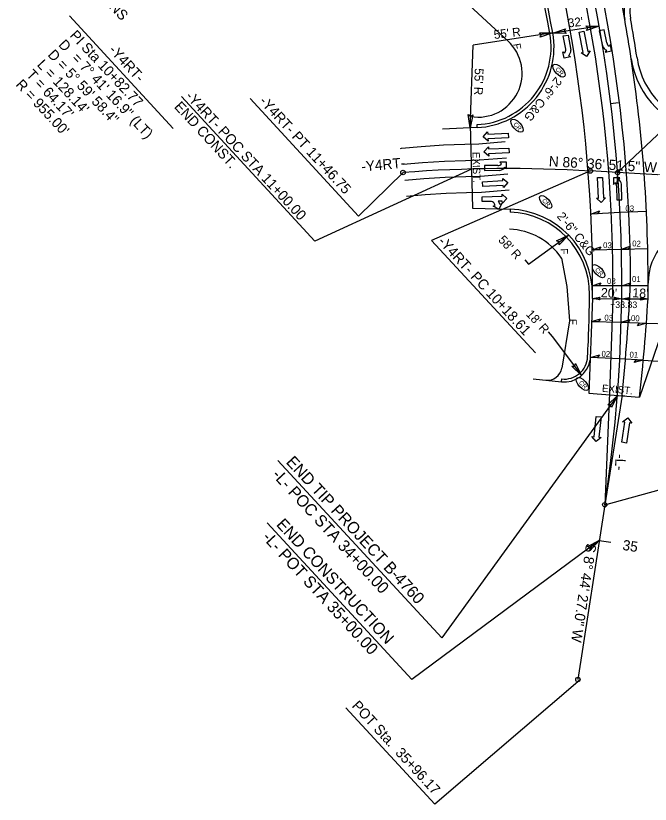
# Model space of a CAD drawing. Extents: x 1702862 to 1704514, y 793768 to 796215.
# Drawn here: x 1703575 to 1704009, y 793768 to 794307 of the extents above; entities that cross this region are included whole.
import ezdxf

# ---------------------------------------------------------------- set-up
doc = ezdxf.new("R2010")
doc.units = 0
for name, color, linetype in [('Exist Horizontal Alignment', 7, 'Continuous'), ('Exist Horizontal Alignment Curve and Spiral Data', 7, 'Continuous'), ('Exist Horizontal Alignment Station Label', 7, 'Continuous'), ('Exist Horizontal Alignment Tick Large', 7, 'Continuous'), ('Prop Conc 2ft 6in Curb and Gutter', 7, 'Continuous'), ('Prop Dimension', 7, 'Continuous'), ('Prop Dimension Text', 7, 'Continuous'), ('Prop DSN Text', 7, 'Continuous'), ('Prop EOT', 7, 'Continuous'), ('Prop Horizontal Alignment', 7, 'Continuous'), ('Prop Horizontal Alignment Curve and Spiral Data', 7, 'Continuous'), ('Prop Horizontal Alignment Direction Label', 7, 'Continuous'), ('Prop Horizontal Alignment Station Label', 7, 'Continuous'), ('Prop Horizontal Alignment Tick Label', 7, 'Continuous'), ('Prop Horizontal Alignment Tick Large', 7, 'Continuous'), ('Prop Horizontal Alignment Tick Small', 7, 'Continuous'), ('Prop Lane Arrow CELL', 7, 'Continuous'), ('Prop Lane Lines', 7, 'Continuous'), ('Prop Leader Line Medium', 7, 'Continuous'), ('Prop Paved Shoulder', 7, 'Continuous'), ('Prop SS Fill Line', 7, 'Continuous'), ('Prop SS Misc', 7, 'Continuous'), ('Prop SS Transition Line', 7, 'Continuous'), ('Prop Superelevation  Arrow CELL', 7, 'Continuous'), ('Prop Superelevation Label', 7, 'Continuous'), ('Prop Terminator CELL', 7, 'Continuous'), ('Prop WCR CELL', 7, 'Continuous')]:
    doc.layers.add(name, color=color, linetype=linetype)

msp = doc.modelspace()

# ---------------------------------------------------------------- linework, layer by layer
at = {"layer": 'Exist Horizontal Alignment'}
msp.add_line((1703986.29, 794199.72), (1703967.71, 794200.82), dxfattribs=at)
msp.add_arc((1703911.32, 793247.48), 955, 86.61431, 94.30234, dxfattribs=at)
at = {"layer": 'Exist Horizontal Alignment Curve and Spiral Data'}
msp.add_line((1703611.73, 794306.9), (1703682.73, 794229.98), dxfattribs=at)
at = {"layer": 'Exist Horizontal Alignment Station Label'}
for p, q in [((1703735.18, 794250.31), (1703809.32, 794169.99)), ((1703809.32, 794169.99), (1703839.67, 794199.79)), ((1703967.71, 794200.82), (1703859.14, 794153.32)), ((1703859.14, 794153.32), (1703930.08, 794076.46))]:
    msp.add_line(p, q, dxfattribs=at)
for centre in [(1703839.67, 794199.79), (1703967.71, 794200.82), (1703986.29, 794199.72)]:
    msp.add_circle(centre, 1.5, dxfattribs=at)
at = {"layer": 'Exist Horizontal Alignment Tick Large'}
msp.add_line((1703986.29, 794199.72), (1703985.82, 794191.73), dxfattribs=at)
at = {"layer": 'Prop Conc 2ft 6in Curb and Gutter'}
for p, q in [((1703890.33, 794230.53), (1703890.23, 794232.53)), ((1703912.86, 794174.66), (1703912.8, 794172.67)), ((1703947.93, 794056.66), (1703948.13, 794058.65))]:
    msp.add_line(p, q, dxfattribs=at)
for centre, radius, start, end in [((1702989.11, 794124.65), 966, 10.14602, 17.69698), ((1703887.83, 794285.48), 53, 272.5979, 10.146), ((1703911.08, 794116.69), 56, 359.5057, 88.2385), ((1702989.11, 794124.65), 978, 357.01557, 359.50571), ((1703949.8, 794074.56), 16, 264.0066, 357.0156)]:
    msp.add_arc(centre, radius, start, end, dxfattribs=at)
at = {"layer": 'Prop Dimension'}
for p, q in [((1703973.64, 794299.88), (1703941.98, 794295.11)), ((1703941.97, 794295.17), (1703887.5, 794286.9)), ((1703885.5, 794230.32), (1703887.5, 794286.9)), ((1703969.03, 794113.76), (1703989.05, 794113.54)), ((1703989.05, 794113.54), (1704007.05, 794113.34))]:
    msp.add_line(p, q, dxfattribs=at)
for points in [[(1703922.81, 794140.12), (1703925.48, 794137.22), (1703952.75, 794157.03)], [(1703938.74, 794090.78), (1703941.53, 794087.76), (1703961.72, 794061.07)]]:
    msp.add_lwpolyline(points, dxfattribs=at)
at = {"layer": 'Prop EOT'}
for p, q in [((1703885.56, 794232.69), (1703886.49, 794197.16)), ((1703890.33, 794230.53), (1703866.68, 794229.46)), ((1703886.36, 794202.16), (1703887.05, 794175.46)), ((1703887.05, 794175.46), (1703912.86, 794174.66)), ((1703969.03, 794113.76), (1703966.73, 794048.94)), ((1703928.6, 794058.69), (1703947.93, 794056.66)), ((1703966.73, 794048.94), (1704001.25, 794046.28))]:
    msp.add_line(p, q, dxfattribs=at)
for centre, radius, start, end in [((1702989.11, 794124.65), 968, 10.14602, 17.69698), ((1704020.66, 794309.61), 30, 121.4124, 190.1653), ((1702989.11, 794124.65), 1018, 8.63399, 10.1653), ((1703887.83, 794285.48), 55, 272.5979, 10.146), ((1704054.89, 794286.48), 60, 188.634, 261.1171), ((1703911.08, 794116.69), 58, 359.5057, 88.2385), ((1704047.11, 794124.17), 40, 97.5132, 179.9743), ((1702989.11, 794124.65), 1018, 359.36375, 359.9743), ((1702989.11, 794124.65), 980, 359.36375, 359.50571), ((1702759.73, 794187.37), 1249.51, 353.51674, 356.60361), ((1703949.8, 794074.56), 18, 264.0066, 349.9892)]:
    msp.add_arc(centre, radius, start, end, dxfattribs=at)
at = {"layer": 'Prop Horizontal Alignment'}
for p, q in [((1704163.59, 794189.23), (1703986.29, 794199.72)), ((1703977.5, 793972.68), (1703959.13, 793853.2))]:
    msp.add_line(p, q, dxfattribs=at)
msp.add_arc((1702989.11, 794124.65), 1000, 351.25916, 42.70907, dxfattribs=at)
at = {"layer": 'Prop Horizontal Alignment Station Label'}
for p, q in [((1703986.29, 794199.72), (1704135, 794340.88)), ((1703977.5, 793972.68), (1704183.79, 794029.59)), ((1703960.61, 793852.97), (1703861.43, 793767.97)), ((1703800.56, 793833.92), (1703861.43, 793767.97))]:
    msp.add_line(p, q, dxfattribs=at)
for centre in [(1703839.67, 794199.79), (1703967.71, 794200.82), (1703986.29, 794199.72), (1703977.5, 793972.68), (1703959.13, 793853.2)]:
    msp.add_circle(centre, 1.5, dxfattribs=at)
at = {"layer": 'Prop Horizontal Alignment Tick Large'}
msp.add_line((1703973.74, 793948.25), (1703981.65, 793947.03), dxfattribs=at)
at = {"layer": 'Prop Horizontal Alignment Tick Small'}
for p, q in [((1703981.59, 794247.06), (1703986.55, 794247.68)), ((1703988.85, 794147.37), (1703993.85, 794147.48)), ((1703986.13, 794047.45), (1703991.11, 794047.06))]:
    msp.add_line(p, q, dxfattribs=at)
at = {"layer": 'Prop Lane Arrow CELL'}
for p, q in [((1703960.02, 794295.65), (1703963.26, 794296.3)), ((1703963.26, 794296.3), (1703966.04, 794282.58)), ((1703977, 794297.33), (1703973.77, 794296.66)), ((1703973.77, 794296.66), (1703975.92, 794286.33)), ((1703978.86, 794288.37), (1703977, 794297.33)), ((1703949.17, 794293.19), (1703952.42, 794293.77)), ((1703950.79, 794284.18), (1703949.17, 794293.19)), ((1703952.42, 794293.77), (1703954.29, 794283.39)), ((1703962.8, 794281.93), (1703960.02, 794295.65)), ((1703981.31, 794287.4), (1703980.5, 794286.16)), ((1703982.18, 794282.98), (1703981.31, 794287.4)), ((1703949.73, 794277.94), (1703948.89, 794282.36)), ((1703948.89, 794282.36), (1703950.11, 794281.52)), ((1703961.33, 794281.63), (1703962.8, 794281.93)), ((1703965.09, 794279.18), (1703961.33, 794281.63)), ((1703967.51, 794282.88), (1703965.09, 794279.18)), ((1703966.04, 794282.58), (1703967.51, 794282.88)), ((1703978.68, 794283.38), (1703977.86, 794282.14)), ((1703977.86, 794282.14), (1703982.18, 794282.98)), ((1703954.05, 794278.77), (1703949.73, 794277.94)), ((1703952.84, 794279.62), (1703954.05, 794278.77)), ((1703894.47, 794224.24), (1703897.48, 794227.58)), ((1703897.48, 794227.58), (1703897.54, 794226.08)), ((1703897.54, 794226.08), (1703911.53, 794226.69)), ((1703911.53, 794226.69), (1703911.67, 794223.39)), ((1703897.75, 794221.28), (1703894.47, 794224.24)), ((1703911.67, 794223.39), (1703897.68, 794222.78)), ((1703897.68, 794222.78), (1703897.75, 794221.28)), ((1703894.95, 794214.02), (1703897.96, 794217.35)), ((1703897.96, 794217.35), (1703898.02, 794215.86)), ((1703898.02, 794215.86), (1703912.01, 794216.46)), ((1703912.01, 794216.46), (1703912.15, 794213.17)), ((1703898.23, 794211.06), (1703894.95, 794214.02)), ((1703912.15, 794213.17), (1703898.17, 794212.56)), ((1703898.17, 794212.56), (1703898.23, 794211.06)), ((1703904.44, 794204.57), (1703895.29, 794204.52)), ((1703895.29, 794204.52), (1703895.31, 794201.22)), ((1703910.38, 794206.75), (1703905.88, 794206.78)), ((1703905.88, 794206.78), (1703906.93, 794205.73)), ((1703910.35, 794202.35), (1703910.38, 794206.75)), ((1703895.31, 794201.22), (1703905.86, 794201.28)), ((1703909.3, 794203.4), (1703910.35, 794202.35)), ((1703893.97, 794193.42), (1703907.94, 794194.3)), ((1703907.94, 794194.3), (1703907.85, 794195.8)), ((1703907.85, 794195.8), (1703911.19, 794192.9)), ((1703972.6, 794196.28), (1703975.89, 794196.44)), ((1703973.27, 794182.3), (1703972.6, 794196.28)), ((1703975.89, 794196.44), (1703976.56, 794182.46)), ((1703987.78, 794196.21), (1703983.38, 794196.19)), ((1703983.38, 794196.19), (1703983.41, 794191.69)), ((1703986.75, 794195.14), (1703987.78, 794196.21)), ((1703894.18, 794190.13), (1703893.97, 794193.42)), ((1703908.15, 794191.01), (1703894.18, 794190.13)), ((1703908.24, 794189.51), (1703908.15, 794191.01)), ((1703911.19, 794192.9), (1703908.24, 794189.51)), ((1703983.41, 794191.69), (1703984.44, 794192.76)), ((1703985.63, 794190.27), (1703985.79, 794181.13)), ((1703989.09, 794181.18), (1703988.91, 794191.73)), ((1703893.64, 794183.22), (1703907.44, 794183.56)), ((1703893.72, 794179.92), (1703893.64, 794183.22)), ((1703907.44, 794183.56), (1703907.4, 794185.06)), ((1703907.4, 794185.06), (1703910.58, 794181.99)), ((1703900.17, 794180.08), (1703893.72, 794179.92)), ((1703907.52, 794180.26), (1703904.67, 794180.19)), ((1703907.26, 794178.55), (1703905.16, 794174.65)), ((1703905.82, 794178.12), (1703907.26, 794178.55)), ((1703907.56, 794178.76), (1703907.52, 794180.26)), ((1703910.58, 794181.99), (1703907.56, 794178.76)), ((1703971.77, 794182.23), (1703973.27, 794182.3)), ((1703975.12, 794179.23), (1703971.77, 794182.23)), ((1703978.06, 794182.53), (1703975.12, 794179.23)), ((1703976.56, 794182.46), (1703978.06, 794182.53)), ((1703985.79, 794181.13), (1703989.09, 794181.18)), ((1703901.25, 794176.75), (1703902.64, 794177.19)), ((1703905.16, 794174.65), (1703901.25, 794176.75)), ((1703970.23, 794019.17), (1703971.68, 794033.09)), ((1703971.68, 794033.09), (1703974.97, 794032.75)), ((1703974.97, 794032.75), (1703973.51, 794018.83)), ((1703989.73, 794029.42), (1703993.28, 794032.06)), ((1703993.28, 794032.06), (1703995.96, 794028.46)), ((1703989.06, 794015.36), (1703991.22, 794029.19)), ((1703991.22, 794029.19), (1703989.73, 794029.42)), ((1703994.48, 794028.69), (1703992.33, 794014.85)), ((1703995.96, 794028.46), (1703994.48, 794028.69)), ((1703971.59, 794015.86), (1703968.74, 794019.33)), ((1703968.74, 794019.33), (1703970.23, 794019.17)), ((1703975, 794018.67), (1703971.59, 794015.86)), ((1703973.51, 794018.83), (1703975, 794018.67)), ((1703992.33, 794014.85), (1703989.06, 794015.36))]:
    msp.add_line(p, q, dxfattribs=at)
for centre, radius, start, end in [((1703980.82, 794288.16), 5.25, 200.4214, 245.7331), ((1703982.06, 794289.03), 3.28, 191.7453, 241.4035), ((1703947.59, 794283.59), 3.28, 320.5495, 10.2077), ((1703949.06, 794283.25), 5.25, 316.22, 1.5316), ((1703904.43, 794207.83), 3.28, 270.3139, 319.9721), ((1703905.04, 794206.45), 5.25, 278.99, 324.3017), ((1703983.75, 794190.85), 5.25, 9.6424, 54.9541), ((1703982.37, 794190.23), 3.28, 0.9663, 50.6245), ((1703899.59, 794177.62), 2.52, 40.4837, 76.7957), ((1703898.32, 794176.18), 4.43, 13.1202, 43.9738), ((1703901.49, 794177.12), 4.43, 13.0014, 43.88)]:
    msp.add_arc(centre, radius, start, end, dxfattribs=at)
at = {"layer": 'Prop Lane Lines'}
for p, q in [((1703983.02, 794113.28), (1703980.78, 794048.9)), ((1703980.78, 794048.9), (1703977.5, 793972.68)), ((1703989.31, 794047.5), (1703977.5, 793972.68))]:
    msp.add_line(p, q, dxfattribs=at)
for points in [[(1703838.03, 794216.26), (1703838.72, 794216.34), (1703852.02, 794217.6), (1703867.42, 794218.64), (1703881.99, 794219.09), (1703891.41, 794219.37), (1703909.53, 794220.88)], [(1703839.86, 794205.39), (1703852.92, 794206.63), (1703867.97, 794207.65), (1703882.32, 794208.1), (1703892.03, 794208.38), (1703910.44, 794209.92)], [(1703840.99, 794194.45), (1703853.81, 794195.67), (1703868.51, 794196.66), (1703882.65, 794197.1), (1703892.65, 794197.4), (1703911.36, 794198.95)], [(1703842.12, 794183.51), (1703854.7, 794184.7), (1703869.05, 794185.67), (1703882.99, 794186.11), (1703893.27, 794186.41), (1703912.27, 794187.99)]]:
    msp.add_lwpolyline(points, dxfattribs=at)
for centre, radius, start, end in [((1702989.11, 794124.65), 1006, 0.00687, 42.70907), ((1702989.11, 794124.65), 994, 359.40932, 42.70907), ((1702989.11, 794124.65), 980, 359.40932, 42.70907), ((1702989.11, 794124.65), 1018, 10.1653, 14.75888), ((1702989.11, 794124.65), 1018, 359.9743, 8.63399), ((1702558.47, 794193.95), 1438.32, 354.15599, 357.24285)]:
    msp.add_arc(centre, radius, start, end, dxfattribs=at)
at = {"layer": 'Prop Leader Line Medium'}
for p, q in [((1703688.26, 794251.68), (1703779.4, 794152.94)), ((1703886.36, 794202.16), (1703779.4, 794152.94)), ((1703986.13, 794047.45), (1703866.27, 793881.64)), ((1703754.24, 794003.01), (1703866.27, 793881.64)), ((1703746.91, 793960.41), (1703845.77, 793853.31)), ((1703973.74, 793948.25), (1703845.77, 793853.31))]:
    msp.add_line(p, q, dxfattribs=at)
at = {"layer": 'Prop Paved Shoulder'}
for centre, radius, start, end in [((1704020.66, 794309.61), 26, 121.4124, 190.1653), ((1702989.11, 794124.65), 1022, 8.63399, 10.1653), ((1704054.89, 794286.48), 56, 188.634, 260.7231)]:
    msp.add_arc(centre, radius, start, end, dxfattribs=at)
at = {"layer": 'Prop SS Fill Line'}
for p, q in [((1703873.4, 794324.92), (1703911.44, 794289.63)), ((1703953.39, 794098.34), (1703948.14, 794066.12))]:
    msp.add_line(p, q, dxfattribs=at)
msp.add_lwpolyline([(1703947.98, 794141.22), (1703951.56, 794121.84), (1703953.39, 794098.34)], dxfattribs=at)
for centre, radius, start, end in [((1703891.03, 794267.64), 30, 260.1886, 47.1443), ((1703911.08, 794116.69), 44.32, 33.6097, 88.2385)]:
    msp.add_arc(centre, radius, start, end, dxfattribs=at)
at = {"layer": 'Prop SS Transition Line'}
msp.add_line((1704018.54, 794096.56), (1704001.25, 794046.28), dxfattribs=at)
msp.add_arc((1703938.27, 794067.73), 10, 264.0066, 350.7431, dxfattribs=at)
at = {"layer": 'Prop Superelevation  Arrow CELL'}
for p, q in [((1703968.48, 794097.93), (1703988.74, 794097.38)), ((1703988.74, 794097.38), (1704005.96, 794096.91)), ((1703987.74, 794072.4), (1703967.77, 794073.44)), ((1704003.62, 794071.57), (1703987.74, 794072.4)), ((1703966.73, 794048.94), (1704001.25, 794046.28))]:
    msp.add_line(p, q, dxfattribs=at)
for points in [[(1703967.99, 794171.4), (1703973.89, 794173.68), (1703972.61, 794171.62)], [(1703968.86, 794146.92), (1703974.81, 794149.06), (1703973.48, 794147.02)], [(1703988.85, 794147.37), (1703994.8, 794149.5), (1703993.48, 794147.47)], [(1703968.79, 794122.42), (1703974.81, 794124.35), (1703973.42, 794122.37)], [(1703989.11, 794122.37), (1703995.13, 794124.29), (1703993.73, 794122.31)], [(1703968.48, 794097.93), (1703974.53, 794099.76), (1703973.1, 794097.8)], [(1703988.74, 794097.38), (1703994.79, 794099.2), (1703993.36, 794097.24)], [(1704005.96, 794096.91), (1703999.92, 794095.05), (1704001.34, 794097.02)], [(1703967.77, 794073.44), (1703973.86, 794075.14), (1703972.39, 794073.21)], [(1704003.62, 794071.57), (1703997.51, 794069.93), (1703999, 794071.84)]]:
    msp.add_lwpolyline(points, close=True, dxfattribs=at)
at = {"layer": 'Prop Superelevation Label'}
for p, q in [((1703987.97, 794172.35), (1703967.99, 794171.4)), ((1704005.95, 794173.21), (1703987.97, 794172.35)), ((1703968.86, 794146.92), (1703988.85, 794147.37)), ((1703988.85, 794147.37), (1704006.85, 794147.78)), ((1703989.11, 794122.37), (1703968.79, 794122.42)), ((1704007.02, 794122.33), (1703989.11, 794122.37)), ((1704005.96, 794096.86), (1704025.4, 794096.22)), ((1704003.62, 794071.57), (1704014.29, 794070.94))]:
    msp.add_line(p, q, dxfattribs=at)
at = {"layer": 'Prop Terminator CELL'}
for points in [[(1703951.11, 794294.92), (1703941.98, 794295.11), (1703950.69, 794298.04), (1703949.79, 794296.29)], [(1703964.51, 794300.08), (1703973.64, 794299.88), (1703964.93, 794296.95), (1703965.82, 794298.71)], [(1703932.84, 794295.36), (1703941.97, 794295.17), (1703933.26, 794292.24), (1703934.16, 794293.99)], [(1703887.36, 794239.26), (1703885.5, 794230.32), (1703884.22, 794239.42), (1703885.78, 794238.21)], [(1703944.56, 794152.99), (1703952.75, 794157.03), (1703946.37, 794150.42), (1703946.36, 794152.39)], [(1703974.19, 794112.82), (1703969.03, 794113.76), (1703974.24, 794114.63), (1703973.57, 794113.71)], [(1703983.88, 794114.49), (1703989.05, 794113.54), (1703983.83, 794112.68), (1703984.51, 794113.59)], [(1703994.23, 794112.59), (1703989.07, 794113.54), (1703994.28, 794114.4), (1703993.61, 794113.49)], [(1704001.88, 794114.29), (1704007.05, 794113.34), (1704001.83, 794112.48), (1704002.5, 794113.39)], [(1703957.53, 794069.18), (1703961.72, 794061.07), (1703954.98, 794067.32), (1703956.95, 794067.37)], [(1703979.6, 794041.06), (1703986.13, 794047.45), (1703982.12, 794039.18), (1703981.5, 794041.05)], [(1703965.63, 793944.05), (1703973.74, 793948.25), (1703967.49, 793941.51), (1703967.44, 793943.48)]]:
    msp.add_lwpolyline(points, close=True, dxfattribs=at)
at = {"layer": 'Prop WCR CELL'}
for centre in [(1703946.19, 794269.44), (1703917.51, 794231.8), (1703937.07, 794179.68), (1703973.26, 794132.33), (1703962.24, 794055.21)]:
    msp.add_ellipse(centre, major_axis=(3.8, -4.12), ratio=0.462467, dxfattribs=at)

# ---------------------------------------------------------------- texts
at = {"layer": 'Exist Horizontal Alignment Curve and Spiral Data'}
for s, rotation, p in [('PI Sta 10+82.77', 313.0501, (1703611.6, 794293.09)), ('D', 313.0501, (1703603.83, 794286.76)), ('-Y4RT-', 312.7091, (1703638.2, 794283.16)), ('D = 5%%d 59\' 58.4"', 313.0501, (1703596.52, 794279.93)), ('= 7%%d 41\' 16.9" (LT)', 313.0501, (1703612.82, 794277.57)), ("L = 128.14'", 313.0501, (1703589.22, 794273.11)), ("T = 64.17'", 313.0501, (1703581.91, 794266.28)), ("R = 955.00'", 313.0501, (1703574.6, 794259.45))]:
    msp.add_text(s, height=7, rotation=rotation, dxfattribs=at).set_placement(p)
at = {"layer": 'Exist Horizontal Alignment Station Label'}
for s, p in [('-Y4RT- PT 11+46.75', (1703741.05, 794248.08)), ('-Y4RT- PC 10+18.61', (1703863.14, 794152.23))]:
    msp.add_text(s, height=7, rotation=312.7091, dxfattribs=at).set_placement(p)
at = {"layer": 'Prop Dimension'}
for s, height, rotation, p in [("32'", 6, 6.4236, (1703952.65, 794298.96)), ("55' R", 6, 6.4236, (1703902, 794291)), ("55' R", 6, 267.9768, (1703888.72, 794271.14)), ("58' R", 6, 312.7091, (1703904.32, 794153.37)), ("20'", 6.3, 356.8874, (1703974.74, 794114.65)), ("18'", 6.3, 356.8874, (1703996.22, 794114.54)), ("18' R", 6, 312.7091, (1703923.3, 794102.61))]:
    msp.add_text(s, height=height, rotation=rotation, dxfattribs=at).set_placement(p)
at = {"layer": 'Prop Dimension Text'}
msp.add_text('2\'-6" C&G', height=6, rotation=231.5769, dxfattribs=at).set_placement((1703944.07, 794265.61))
at = {"layer": 'Prop DSN Text'}
for s, height, rotation, p in [('-Y4RT- POC STA 11+00.00', 7, 312.7091, (1703690.63, 794251.52)), ('END CONST.', 7, 312.7091, (1703682.92, 794244.4)), ('EXIST.', 5, 271.4976, (1703887.11, 794213.81)), ('2\'-6" C&G', 6, 309.2167, (1703944.48, 794169.7)), ('EXIST.', 5, 354.8849, (1703975.39, 794049.95)), ('END TIP PROJECT B-4760', 8, 312.7091, (1703759.29, 794001.5)), ('-L- POC STA 34+00.00', 8, 312.7091, (1703749.74, 793992.69)), ('END CONSTRUCTION', 8, 312.7091, (1703752.63, 793958.8)), ('-L- POT STA 35+00.00', 8, 312.7091, (1703743.08, 793949.98))]:
    msp.add_text(s, height=height, rotation=rotation, dxfattribs=at).set_placement(p)
at = {"layer": 'Prop Horizontal Alignment Curve and Spiral Data'}
msp.add_text('e = SEE PLANS', height=7, rotation=312.7091, dxfattribs=at).set_placement((1703601.35, 794353.03))
at = {"layer": 'Prop Horizontal Alignment Direction Label'}
for s, rotation, p in [('-Y4RT-', 5.163, (1703811.43, 794200.4)), ('N 86%%d 36\' 51.5" W', 356.6143, (1703939.12, 794204.07)), ('-L-', 267.3709, (1703984.92, 794007.51)), ('S 8%%d 44\' 27.0" W', 261.2592, (1703964.88, 793946.61))]:
    msp.add_text(s, height=7, rotation=rotation, dxfattribs=at).set_placement(p)
at = {"layer": 'Prop Horizontal Alignment Station Label'}
msp.add_text('POT Sta.  35+96.17', height=7, rotation=312.7091, dxfattribs=at).set_placement((1703804.31, 793834.88))
at = {"layer": 'Prop Horizontal Alignment Tick Label'}
msp.add_text('35', height=7, rotation=351.2592, dxfattribs=at).set_placement((1703989.28, 793941.88))
at = {"layer": 'Prop SS Misc'}
for rotation, p in [(279.8964, (1703914.89, 794287.6)), (271.3021, (1703947.3, 794147.84)), (268.4373, (1703953.43, 794099.76))]:
    msp.add_text('F', height=5, rotation=rotation, dxfattribs=at).set_placement(p)
at = {"layer": 'Prop Superelevation Label'}
for s, height, rotation, p in [('03', 4, 357.7211, (1703991.52, 794173.38)), ('03', 4, 357.7211, (1703976.28, 794148.19)), ('02', 4, 357.7211, (1703996.15, 794149.35)), ('01', 4, 357.7211, (1703996.04, 794125.07)), ('03', 4, 357.7211, (1703978.95, 794123.67)), ('+33.83', 4.5, 359.4566, (1703981.12, 794107.26)), ('03', 4, 357.7211, (1703977.17, 794098.6)), ('00', 4, 357.7211, (1703995.32, 794098.28)), ('02', 4, 357.7211, (1703975.19, 794073.91)), ('01', 4, 357.7211, (1703994.32, 794073.32))]:
    msp.add_text(s, height=height, rotation=rotation, dxfattribs=at).set_placement(p)
at = {"layer": 'Prop WCR CELL'}
for p in [(1703943.5, 794270.17), (1703914.83, 794232.53), (1703934.39, 794180.41), (1703970.57, 794133.06), (1703959.56, 794055.94)]:
    msp.add_text('CR', height=3, rotation=312.7091, dxfattribs=at).set_placement(p)

doc.saveas('drawing.dxf')
